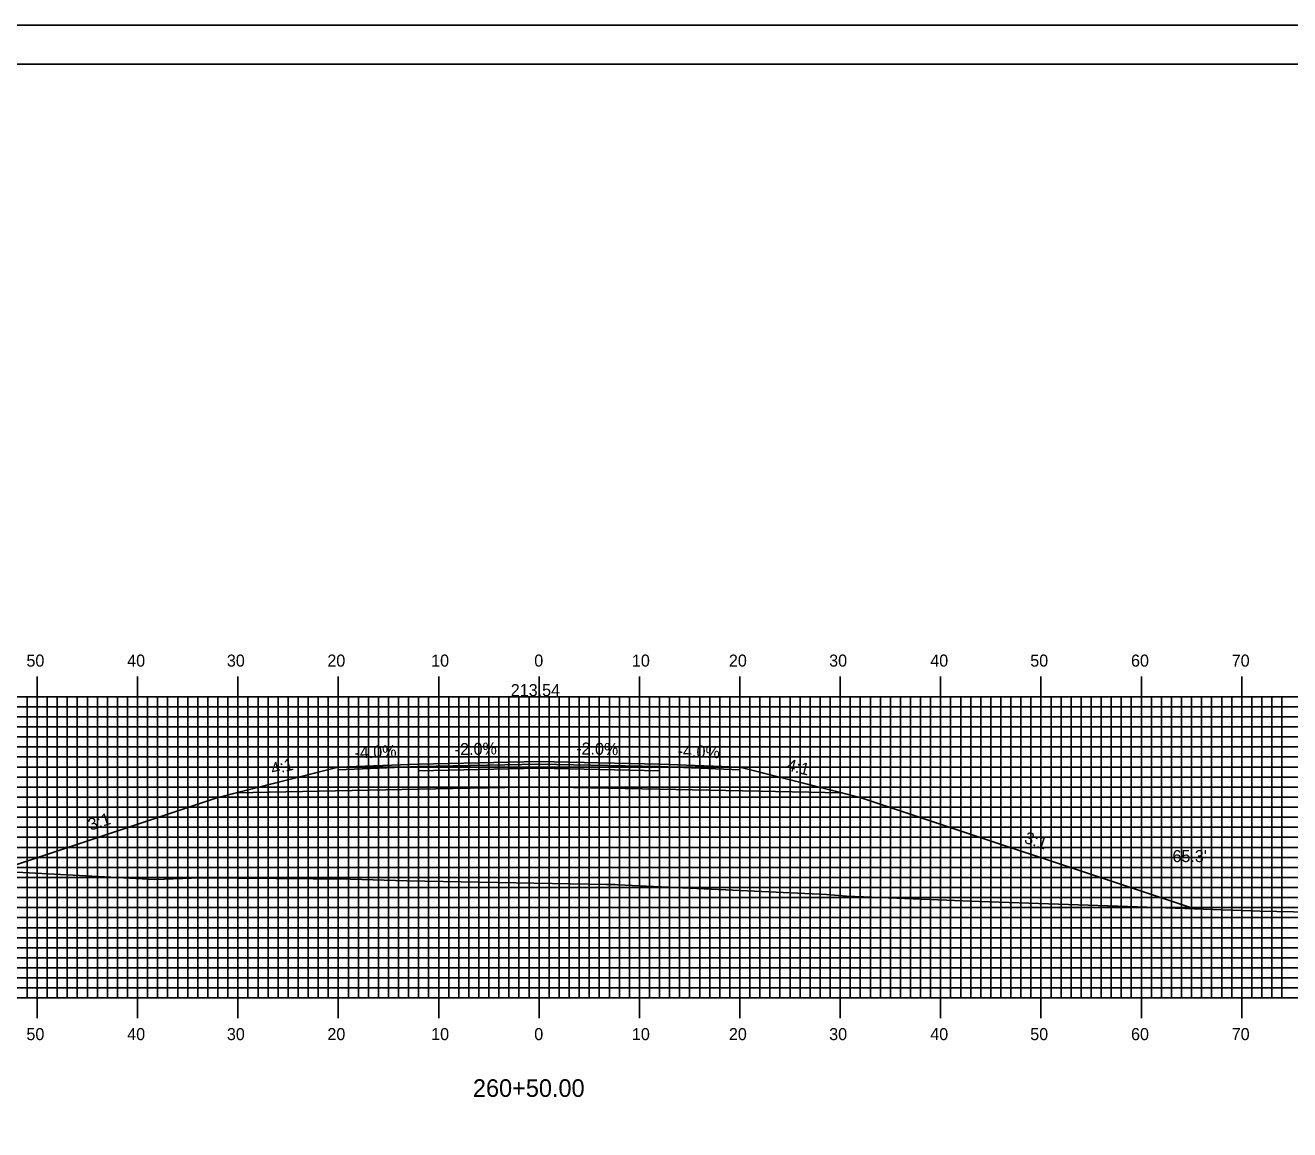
# Model space of a CAD drawing. Extents: x 1805864 to 1806208, y 442591 to 442811.
# Drawn here: x 1805979 to 1806105, y 442700.5 to 442810.5 of the extents above; entities that cross this region are included whole.
import ezdxf

# ---------------------------------------------------------------- set-up
doc = ezdxf.new("R2010")
doc.units = 0
for name, color, linetype in [('ANNOTATION', 7, 'Continuous'), ('BORDER', 7, 'Continuous'), ('D_Roadway_Centerline', 7, 'Continuous'), ('D_Roadway_Centerline_Text', 7, 'Continuous'), ('D_Roadway_Edge_Shoulder', 7, 'Continuous'), ('D_Roadway_Edge_TW', 7, 'Continuous'), ('D_Roadway_Pavement', 7, 'Continuous'), ('D_Roadway_SlopeLines', 7, 'Continuous'), ('D_Roadway_SubGrade', 7, 'Continuous'), ('D_Text_Standard', 7, 'Continuous'), ('H_V ANNOTATION', 7, 'Continuous'), ('MAJOR', 7, 'Continuous'), ('MINOR', 7, 'Continuous'), ('PLOT BOUNDARY', 7, 'Continuous'), ('S_Roadway_Centerline', 7, 'Continuous')]:
    doc.layers.add(name, color=color, linetype=linetype)

msp = doc.modelspace()

# ---------------------------------------------------------------- linework, layer by layer
at = {"layer": 'BORDER'}
msp.add_lwpolyline([(1805880.62, 442596.67), (1806200.62, 442596.67), (1806200.62, 442806.67), (1805880.62, 442806.67)], close=True, dxfattribs=at)
at = {"layer": 'D_Roadway_Centerline'}
msp.add_lwpolyline([(1805976.16, 442726.29), (1805998.22, 442733.65), (1806000.05, 442734.1), (1806010.22, 442736.65), (1806018.22, 442736.97), (1806030.22, 442737.21), (1806042.22, 442736.97), (1806050.22, 442736.65), (1806060.39, 442734.1), (1806062.22, 442733.65), (1806095.51, 442722.55)], dxfattribs=at)
at = {"layer": 'D_Roadway_Edge_Shoulder'}
for points in [[(1806018.22, 442736.97), (1806010.22, 442736.65), (1806010.22, 442736.4), (1806018.22, 442736.72)], [(1806042.22, 442736.97), (1806050.22, 442736.65), (1806050.22, 442736.4), (1806042.22, 442736.72)]]:
    msp.add_lwpolyline(points, close=True, dxfattribs=at)
at = {"layer": 'D_Roadway_Edge_TW'}
msp.add_lwpolyline([(1806018.22, 442736.72), (1806018.22, 442736.97), (1806030.22, 442737.21), (1806042.22, 442736.97), (1806042.22, 442736.72), (1806030.22, 442736.96)], close=True, dxfattribs=at)
at = {"layer": 'D_Roadway_Pavement'}
msp.add_lwpolyline([(1806018.22, 442736.3), (1806018.22, 442736.72), (1806030.22, 442736.96), (1806042.22, 442736.72), (1806042.22, 442736.3), (1806030.22, 442736.54)], close=True, dxfattribs=at)
at = {"layer": 'D_Roadway_SlopeLines'}
for points in [[(1806010.22, 442736.65), (1805998.22, 442733.65), (1805976.16, 442726.29)], [(1806050.22, 442736.65), (1806062.22, 442733.65), (1806095.51, 442722.55)]]:
    msp.add_lwpolyline(points, dxfattribs=at)
at = {"layer": 'D_Roadway_SubGrade'}
msp.add_lwpolyline([(1806018.22, 442734.47), (1806000.05, 442734.1), (1806010.22, 442736.65), (1806010.22, 442736.4), (1806018.22, 442736.72), (1806030.22, 442736.96), (1806042.22, 442736.72), (1806050.22, 442736.4), (1806050.22, 442736.65), (1806060.39, 442734.1), (1806042.22, 442734.47), (1806030.22, 442734.71)], close=True, dxfattribs=at)
at = {"layer": 'MAJOR'}
for p, q in [((1805980.22, 442745.67), (1805980.22, 442743.67)), ((1805990.22, 442745.67), (1805990.22, 442743.67)), ((1806000.22, 442745.67), (1806000.22, 442743.67)), ((1806010.22, 442745.67), (1806010.22, 442743.67)), ((1806020.22, 442745.67), (1806020.22, 442743.67)), ((1806030.22, 442745.67), (1806030.22, 442743.67)), ((1806040.22, 442745.67), (1806040.22, 442743.67)), ((1806050.22, 442745.67), (1806050.22, 442743.67)), ((1806060.22, 442745.67), (1806060.22, 442743.67)), ((1806070.22, 442745.67), (1806070.22, 442743.67)), ((1806080.22, 442745.67), (1806080.22, 442743.67)), ((1806090.22, 442745.67), (1806090.22, 442743.67)), ((1806100.22, 442745.67), (1806100.22, 442743.67)), ((1805890.22, 442743.67), (1806170.22, 442743.67)), ((1805890.22, 442743.67), (1806170.22, 442743.67)), ((1805980.22, 442713.67), (1805980.22, 442743.67)), ((1805990.22, 442713.67), (1805990.22, 442743.67)), ((1806000.22, 442713.67), (1806000.22, 442743.67)), ((1806010.22, 442713.67), (1806010.22, 442743.67)), ((1806020.22, 442713.67), (1806020.22, 442743.67)), ((1806030.22, 442713.67), (1806030.22, 442743.67)), ((1806040.22, 442713.67), (1806040.22, 442743.67)), ((1806050.22, 442713.67), (1806050.22, 442743.67)), ((1806060.22, 442713.67), (1806060.22, 442743.67)), ((1806070.22, 442713.67), (1806070.22, 442743.67)), ((1806080.22, 442713.67), (1806080.22, 442743.67)), ((1806090.22, 442713.67), (1806090.22, 442743.67)), ((1806100.22, 442713.67), (1806100.22, 442743.67)), ((1805890.22, 442738.67), (1806170.22, 442738.67)), ((1805890.22, 442733.67), (1806170.22, 442733.67)), ((1805890.22, 442728.67), (1806170.22, 442728.67)), ((1805890.22, 442723.67), (1806170.22, 442723.67)), ((1805890.22, 442718.67), (1806170.22, 442718.67)), ((1805890.22, 442713.67), (1806170.22, 442713.67)), ((1805890.22, 442713.67), (1806170.22, 442713.67)), ((1805980.22, 442711.66), (1805980.22, 442713.67)), ((1805990.22, 442711.66), (1805990.22, 442713.67)), ((1806000.22, 442711.66), (1806000.22, 442713.67)), ((1806010.22, 442711.66), (1806010.22, 442713.67)), ((1806020.22, 442711.66), (1806020.22, 442713.67)), ((1806030.22, 442711.66), (1806030.22, 442713.67)), ((1806040.22, 442711.66), (1806040.22, 442713.67)), ((1806050.22, 442711.66), (1806050.22, 442713.67)), ((1806060.22, 442711.66), (1806060.22, 442713.67)), ((1806070.22, 442711.66), (1806070.22, 442713.67)), ((1806080.22, 442711.66), (1806080.22, 442713.67)), ((1806090.22, 442711.66), (1806090.22, 442713.67)), ((1806100.22, 442711.66), (1806100.22, 442713.67))]:
    msp.add_line(p, q, dxfattribs=at)
at = {"layer": 'MINOR'}
for p, q in [((1805979.22, 442713.67), (1805979.22, 442743.67)), ((1805981.22, 442713.67), (1805981.22, 442743.67)), ((1805982.22, 442713.67), (1805982.22, 442743.67)), ((1805983.22, 442713.67), (1805983.22, 442743.67)), ((1805984.22, 442713.67), (1805984.22, 442743.67)), ((1805985.22, 442713.67), (1805985.22, 442743.67)), ((1805986.22, 442713.67), (1805986.22, 442743.67)), ((1805987.22, 442713.67), (1805987.22, 442743.67)), ((1805988.22, 442713.67), (1805988.22, 442743.67)), ((1805989.22, 442713.67), (1805989.22, 442743.67)), ((1805991.22, 442713.67), (1805991.22, 442743.67)), ((1805992.22, 442713.67), (1805992.22, 442743.67)), ((1805993.22, 442713.67), (1805993.22, 442743.67)), ((1805994.22, 442713.67), (1805994.22, 442743.67)), ((1805995.22, 442713.67), (1805995.22, 442743.67)), ((1805996.22, 442713.67), (1805996.22, 442743.67)), ((1805997.22, 442713.67), (1805997.22, 442743.67)), ((1805998.22, 442713.67), (1805998.22, 442743.67)), ((1805999.22, 442713.67), (1805999.22, 442743.67)), ((1806001.22, 442713.67), (1806001.22, 442743.67)), ((1806002.22, 442713.67), (1806002.22, 442743.67)), ((1806003.22, 442713.67), (1806003.22, 442743.67)), ((1806004.22, 442713.67), (1806004.22, 442743.67)), ((1806005.22, 442713.67), (1806005.22, 442743.67)), ((1806006.22, 442713.67), (1806006.22, 442743.67)), ((1806007.22, 442713.67), (1806007.22, 442743.67)), ((1806008.22, 442713.67), (1806008.22, 442743.67)), ((1806009.22, 442713.67), (1806009.22, 442743.67)), ((1806011.22, 442713.67), (1806011.22, 442743.67)), ((1806012.22, 442713.67), (1806012.22, 442743.67)), ((1806013.22, 442713.67), (1806013.22, 442743.67)), ((1806014.22, 442713.67), (1806014.22, 442743.67)), ((1806015.22, 442713.67), (1806015.22, 442743.67)), ((1806016.22, 442713.67), (1806016.22, 442743.67)), ((1806017.22, 442713.67), (1806017.22, 442743.67)), ((1806018.22, 442713.67), (1806018.22, 442743.67)), ((1806019.22, 442713.67), (1806019.22, 442743.67)), ((1806021.22, 442713.67), (1806021.22, 442743.67)), ((1806022.22, 442713.67), (1806022.22, 442743.67)), ((1806023.22, 442713.67), (1806023.22, 442743.67)), ((1806024.22, 442713.67), (1806024.22, 442743.67)), ((1806025.22, 442713.67), (1806025.22, 442743.67)), ((1806026.22, 442713.67), (1806026.22, 442743.67)), ((1806027.22, 442713.67), (1806027.22, 442743.67)), ((1806028.22, 442713.67), (1806028.22, 442743.67)), ((1806029.22, 442713.67), (1806029.22, 442743.67)), ((1806031.22, 442713.67), (1806031.22, 442743.67)), ((1806032.22, 442713.67), (1806032.22, 442743.67)), ((1806033.22, 442713.67), (1806033.22, 442743.67)), ((1806034.22, 442713.67), (1806034.22, 442743.67)), ((1806035.22, 442713.67), (1806035.22, 442743.67)), ((1806036.22, 442713.67), (1806036.22, 442743.67)), ((1806037.22, 442713.67), (1806037.22, 442743.67)), ((1806038.22, 442713.67), (1806038.22, 442743.67)), ((1806039.22, 442713.67), (1806039.22, 442743.67)), ((1806041.22, 442713.67), (1806041.22, 442743.67)), ((1806042.22, 442713.67), (1806042.22, 442743.67)), ((1806043.22, 442713.67), (1806043.22, 442743.67)), ((1806044.22, 442713.67), (1806044.22, 442743.67)), ((1806045.22, 442713.67), (1806045.22, 442743.67)), ((1806046.22, 442713.67), (1806046.22, 442743.67)), ((1806047.22, 442713.67), (1806047.22, 442743.67)), ((1806048.22, 442713.67), (1806048.22, 442743.67)), ((1806049.22, 442713.67), (1806049.22, 442743.67)), ((1806051.22, 442713.67), (1806051.22, 442743.67)), ((1806052.22, 442713.67), (1806052.22, 442743.67)), ((1806053.22, 442713.67), (1806053.22, 442743.67)), ((1806054.22, 442713.67), (1806054.22, 442743.67)), ((1806055.22, 442713.67), (1806055.22, 442743.67)), ((1806056.22, 442713.67), (1806056.22, 442743.67)), ((1806057.22, 442713.67), (1806057.22, 442743.67)), ((1806058.22, 442713.67), (1806058.22, 442743.67)), ((1806059.22, 442713.67), (1806059.22, 442743.67)), ((1806061.22, 442713.67), (1806061.22, 442743.67)), ((1806062.22, 442713.67), (1806062.22, 442743.67)), ((1806063.22, 442713.67), (1806063.22, 442743.67)), ((1806064.22, 442713.67), (1806064.22, 442743.67)), ((1806065.22, 442713.67), (1806065.22, 442743.67)), ((1806066.22, 442713.67), (1806066.22, 442743.67)), ((1806067.22, 442713.67), (1806067.22, 442743.67)), ((1806068.22, 442713.67), (1806068.22, 442743.67)), ((1806069.22, 442713.67), (1806069.22, 442743.67)), ((1806071.22, 442713.67), (1806071.22, 442743.67)), ((1806072.22, 442713.67), (1806072.22, 442743.67)), ((1806073.22, 442713.67), (1806073.22, 442743.67)), ((1806074.22, 442713.67), (1806074.22, 442743.67)), ((1806075.22, 442713.67), (1806075.22, 442743.67)), ((1806076.22, 442713.67), (1806076.22, 442743.67)), ((1806077.22, 442713.67), (1806077.22, 442743.67)), ((1806078.22, 442713.67), (1806078.22, 442743.67)), ((1806079.22, 442713.67), (1806079.22, 442743.67)), ((1806081.22, 442713.67), (1806081.22, 442743.67)), ((1806082.22, 442713.67), (1806082.22, 442743.67)), ((1806083.22, 442713.67), (1806083.22, 442743.67)), ((1806084.22, 442713.67), (1806084.22, 442743.67)), ((1806085.22, 442713.67), (1806085.22, 442743.67)), ((1806086.22, 442713.67), (1806086.22, 442743.67)), ((1806087.22, 442713.67), (1806087.22, 442743.67)), ((1806088.22, 442713.67), (1806088.22, 442743.67)), ((1806089.22, 442713.67), (1806089.22, 442743.67)), ((1806091.22, 442713.67), (1806091.22, 442743.67)), ((1806092.22, 442713.67), (1806092.22, 442743.67)), ((1806093.22, 442713.67), (1806093.22, 442743.67)), ((1806094.22, 442713.67), (1806094.22, 442743.67)), ((1806095.22, 442713.67), (1806095.22, 442743.67)), ((1806096.22, 442713.67), (1806096.22, 442743.67)), ((1806097.22, 442713.67), (1806097.22, 442743.67)), ((1806098.22, 442713.67), (1806098.22, 442743.67)), ((1806099.22, 442713.67), (1806099.22, 442743.67)), ((1806101.22, 442713.67), (1806101.22, 442743.67)), ((1806102.22, 442713.67), (1806102.22, 442743.67)), ((1806103.22, 442713.67), (1806103.22, 442743.67)), ((1806104.22, 442713.67), (1806104.22, 442743.67)), ((1805890.22, 442742.67), (1806170.22, 442742.67)), ((1805890.22, 442741.67), (1806170.22, 442741.67)), ((1805890.22, 442740.67), (1806170.22, 442740.67)), ((1805890.22, 442739.67), (1806170.22, 442739.67)), ((1805890.22, 442737.67), (1806170.22, 442737.67)), ((1805890.22, 442736.67), (1806170.22, 442736.67)), ((1805890.22, 442735.67), (1806170.22, 442735.67)), ((1805890.22, 442734.67), (1806170.22, 442734.67)), ((1805890.22, 442732.67), (1806170.22, 442732.67)), ((1805890.22, 442731.67), (1806170.22, 442731.67)), ((1805890.22, 442730.67), (1806170.22, 442730.67)), ((1805890.22, 442729.67), (1806170.22, 442729.67)), ((1805890.22, 442727.67), (1806170.22, 442727.67)), ((1805890.22, 442726.67), (1806170.22, 442726.67)), ((1805890.22, 442725.67), (1806170.22, 442725.67)), ((1805890.22, 442724.67), (1806170.22, 442724.67)), ((1805890.22, 442722.67), (1806170.22, 442722.67)), ((1805890.22, 442721.67), (1806170.22, 442721.67)), ((1805890.22, 442720.67), (1806170.22, 442720.67)), ((1805890.22, 442719.67), (1806170.22, 442719.67)), ((1805890.22, 442717.67), (1806170.22, 442717.67)), ((1805890.22, 442716.67), (1806170.22, 442716.67)), ((1805890.22, 442715.67), (1806170.22, 442715.67)), ((1805890.22, 442714.67), (1806170.22, 442714.67))]:
    msp.add_line(p, q, dxfattribs=at)
at = {"layer": 'PLOT BOUNDARY'}
msp.add_lwpolyline([(1805864.43, 442590.55), (1806204.43, 442590.55), (1806204.43, 442810.55), (1805864.43, 442810.55)], close=True, dxfattribs=at)
at = {"layer": 'S_Roadway_Centerline'}
msp.add_lwpolyline([(1805974.38, 442726.39), (1805991.94, 442725.48), (1805996.54, 442725.64), (1806011.45, 442725.51), (1806017.05, 442725.32), (1806036.94, 442724.98), (1806037.8, 442724.96), (1806038.06, 442724.95), (1806058.86, 442723.96), (1806060.86, 442723.81), (1806063.38, 442723.72), (1806074.08, 442723.27), (1806089.83, 442722.76), (1806102.05, 442722.31), (1806110.33, 442722.16), (1806133.52, 442721.8), (1806143.84, 442721.33), (1806151.57, 442721.26), (1806159.64, 442721.15), (1806170.22, 442720.68)], dxfattribs=at)

# ---------------------------------------------------------------- texts
at = {"layer": 'ANNOTATION'}
for s, rotation, p in [('-4.0%', 2.2906, (1806011.85, 442737.51)), ('-2.0%', 1.1458, (1806021.83, 442737.84)), ('-2.0%', 358.8542, (1806033.91, 442737.93)), ('-4.0%', 357.7094, (1806044.01, 442737.7)), ('4:1', 14.0362, (1806003.67, 442735.87)), ('4:1', 345.9638, (1806054.81, 442736.36)), ('3:1', 18.4348, (1805985.53, 442730.32)), ('3:1', 341.5652, (1806078.47, 442729.14))]:
    msp.add_text(s, height=1.2, rotation=rotation, dxfattribs=at).set_placement(p)
at = {"layer": 'D_Roadway_Centerline'}
for s, p in [('C', (1806030.21, 442737.21)), ('L', (1806030.22, 442737.2))]:
    msp.add_text(s, height=0.0146, dxfattribs=at).set_placement(p)
at = {"layer": 'D_Roadway_Centerline_Text'}
msp.add_text('213.54', height=1.2, dxfattribs=at).set_placement((1806027.4, 442743.73))
at = {"layer": 'D_Text_Standard'}
msp.add_text("65.3'", height=1.2, dxfattribs=at).set_placement((1806093.32, 442727.2))
at = {"layer": 'H_V ANNOTATION'}
for s, height, p in [('50', 1.2, (1805979.15, 442746.67)), ('40', 1.2, (1805989.19, 442746.67)), ('30', 1.2, (1805999.12, 442746.67)), ('20', 1.2, (1806009.13, 442746.67)), ('10', 1.2, (1806019.47, 442746.67)), ('0', 1.2, (1806029.74, 442746.67)), ('10', 1.2, (1806039.47, 442746.67)), ('20', 1.2, (1806049.13, 442746.67)), ('30', 1.2, (1806059.12, 442746.67)), ('40', 1.2, (1806069.19, 442746.67)), ('50', 1.2, (1806079.15, 442746.67)), ('60', 1.2, (1806089.19, 442746.67)), ('70', 1.2, (1806099.22, 442746.67)), ('50', 1.2, (1805979.15, 442709.47)), ('40', 1.2, (1805989.19, 442709.47)), ('30', 1.2, (1805999.12, 442709.47)), ('20', 1.2, (1806009.13, 442709.47)), ('10', 1.2, (1806019.47, 442709.47)), ('0', 1.2, (1806029.74, 442709.47)), ('10', 1.2, (1806039.47, 442709.47)), ('20', 1.2, (1806049.13, 442709.47)), ('30', 1.2, (1806059.12, 442709.47)), ('40', 1.2, (1806069.19, 442709.47)), ('50', 1.2, (1806079.15, 442709.47)), ('60', 1.2, (1806089.19, 442709.47)), ('70', 1.2, (1806099.22, 442709.47)), ('260+50.00', 1.75, (1806023.63, 442703.82))]:
    msp.add_text(s, height=height, dxfattribs=at).set_placement(p)

doc.saveas('drawing.dxf')
